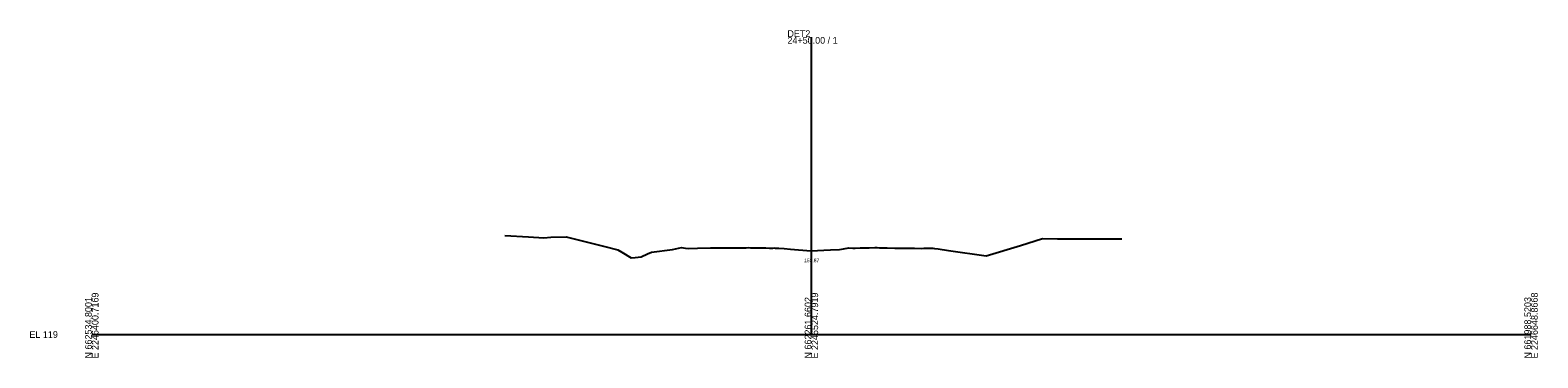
# Model space of a CAD drawing. Extents: x -26 to 603, y -10 to 9526.
# Drawn here: x -26 to 603, y 7490 to 7627 of the extents above; entities that cross this region are included whole.
import ezdxf

# ---------------------------------------------------------------- set-up
doc = ezdxf.new("R2010")
doc.units = 0
for name, color, linetype in [('Default', 7, 'Continuous'), ('Exist Cross Section Cell', 7, 'Continuous'), ('Exist XS Center Line Elevation Label', 7, 'Continuous'), ('Exist XS Ground Line', 7, 'Continuous')]:
    doc.layers.add(name, color=color, linetype=linetype)

msp = doc.modelspace()

# ---------------------------------------------------------------- linework, layer by layer
at = {"layer": 'Exist Cross Section Cell'}
for p, q in [((300, 7500), (300, 7623.9)), ((0, 7500), (300, 7500)), ((300, 7500), (600, 7500))]:
    msp.add_line(p, q, dxfattribs=at)
at = {"layer": 'Exist XS Ground Line'}
for p, q in [((172.19, 7541.3), (182.01, 7540.7)), ((182.01, 7540.7), (188.51, 7540.32)), ((188.51, 7540.32), (191.36, 7540.5)), ((191.36, 7540.5), (197.81, 7540.72)), ((197.81, 7540.72), (213.89, 7536.63)), ((213.89, 7536.63), (219.33, 7535.26)), ((242.11, 7535.44), (245.84, 7536.21)), ((245.84, 7536.21), (247.45, 7536.01)), ((257.94, 7536.08), (261.7, 7536.14)), ((261.7, 7536.14), (263.65, 7536.07)), ((268.87, 7536.1), (271.2, 7536.12)), ((271.2, 7536.12), (272.79, 7536.14)), ((272.79, 7536.14), (273.74, 7536.25)), ((273.74, 7536.25), (274.6, 7536.14)), ((274.6, 7536.14), (274.98, 7536.13)), ((274.98, 7536.13), (276.32, 7536.11)), ((276.32, 7536.11), (278.75, 7536.07)), ((324.11, 7536.1), (326.47, 7536.18)), ((326.47, 7536.18), (326.98, 7536.23)), ((326.98, 7536.23), (327.4, 7536.19)), ((327.4, 7536.19), (328.43, 7536.12)), ((328.43, 7536.12), (329.28, 7536.11)), ((329.28, 7536.11), (331.62, 7536.07)), ((372.87, 7532.78), (387.15, 7537.13)), ((387.15, 7537.13), (396.39, 7539.96)), ((396.39, 7539.96), (402.56, 7539.89)), ((402.56, 7539.89), (407.04, 7539.91)), ((407.04, 7539.91), (429.4, 7539.9)), ((219.33, 7535.26), (220.99, 7534.24)), ((220.99, 7534.24), (224.9, 7532)), ((224.9, 7532), (226.51, 7532.14)), ((226.51, 7532.14), (229.01, 7532.3)), ((229.01, 7532.3), (231.7, 7533.58)), ((231.7, 7533.58), (233.34, 7534.32)), ((233.34, 7534.32), (242.11, 7535.44)), ((247.45, 7536.01), (248.65, 7535.85)), ((248.65, 7535.85), (252.47, 7536.01)), ((252.47, 7536.01), (257.94, 7536.08)), ((263.65, 7536.07), (264.23, 7536.07)), ((264.23, 7536.07), (267.42, 7536.09)), ((267.42, 7536.09), (268.87, 7536.1)), ((278.75, 7536.07), (281.05, 7536.04)), ((281.05, 7536.04), (282.53, 7536.02)), ((282.53, 7536.02), (283.94, 7536.03)), ((283.94, 7536.03), (284.65, 7536.04)), ((284.65, 7536.04), (285.05, 7535.97)), ((285.05, 7535.97), (285.77, 7535.96)), ((285.77, 7535.96), (286.48, 7535.92)), ((286.48, 7535.92), (288.65, 7535.79)), ((288.65, 7535.79), (291.34, 7535.55)), ((291.34, 7535.55), (299.81, 7534.86)), ((299.81, 7534.86), (307.95, 7535.29)), ((307.95, 7535.29), (311.75, 7535.43)), ((311.75, 7535.43), (313.35, 7535.71)), ((313.35, 7535.71), (315.6, 7536.06)), ((315.6, 7536.06), (317.24, 7535.97)), ((317.24, 7535.97), (318.3, 7535.99)), ((318.3, 7535.99), (320.29, 7536.04)), ((320.29, 7536.04), (323.79, 7536.1)), ((323.79, 7536.1), (324.11, 7536.1)), ((331.62, 7536.07), (334.77, 7536.03)), ((334.77, 7536.03), (335.4, 7536.02)), ((335.4, 7536.02), (338.74, 7536.01)), ((338.74, 7536.01), (339.18, 7536.01)), ((339.18, 7536.01), (339.48, 7535.99)), ((339.48, 7535.99), (340.27, 7535.96)), ((340.27, 7535.96), (342.95, 7535.94)), ((342.95, 7535.94), (345.76, 7535.89)), ((345.76, 7535.89), (346.84, 7535.9)), ((346.84, 7535.9), (348.55, 7535.99)), ((348.55, 7535.99), (348.93, 7535.96)), ((348.93, 7535.96), (350.6, 7535.95)), ((350.6, 7535.95), (351.25, 7535.87)), ((351.25, 7535.87), (352.84, 7535.69)), ((352.84, 7535.69), (357.22, 7535.06)), ((357.22, 7535.06), (372.87, 7532.78))]:
    msp.add_line(p, q, dxfattribs=at)

# ---------------------------------------------------------------- texts
at = {"layer": 'Default'}
msp.add_text('-', height=0.0001, dxfattribs=at).set_placement((0, 7500))
msp.add_text('-', height=0.0001, dxfattribs=at).set_placement((0, 7500))
at = {"layer": 'Exist Cross Section Cell'}
for s, p in [('DET2', (290, 7623.9)), ('24+50.00 / 1', (290, 7621.1)), ('EL 119', (-26, 7498.6))]:
    msp.add_text(s, height=2.8, dxfattribs=at).set_placement(p)
for s, p in [('E 2246400.7169', (2.8, 7490)), ('E 2246524.7919', (302.8, 7490)), ('E 2246648.8668', (602.8, 7490)), ('N 662534.8001', (0, 7490)), ('N 662261.6602', (300, 7490)), ('N 661988.5203', (600, 7490))]:
    msp.add_text(s, height=2.8, rotation=90, dxfattribs=at).set_placement(p)
at = {"layer": 'Exist XS Center Line Elevation Label'}
msp.add_text('153.87', height=1.5, dxfattribs=at).set_placement((296.95, 7530.12))

doc.saveas('drawing.dxf')
